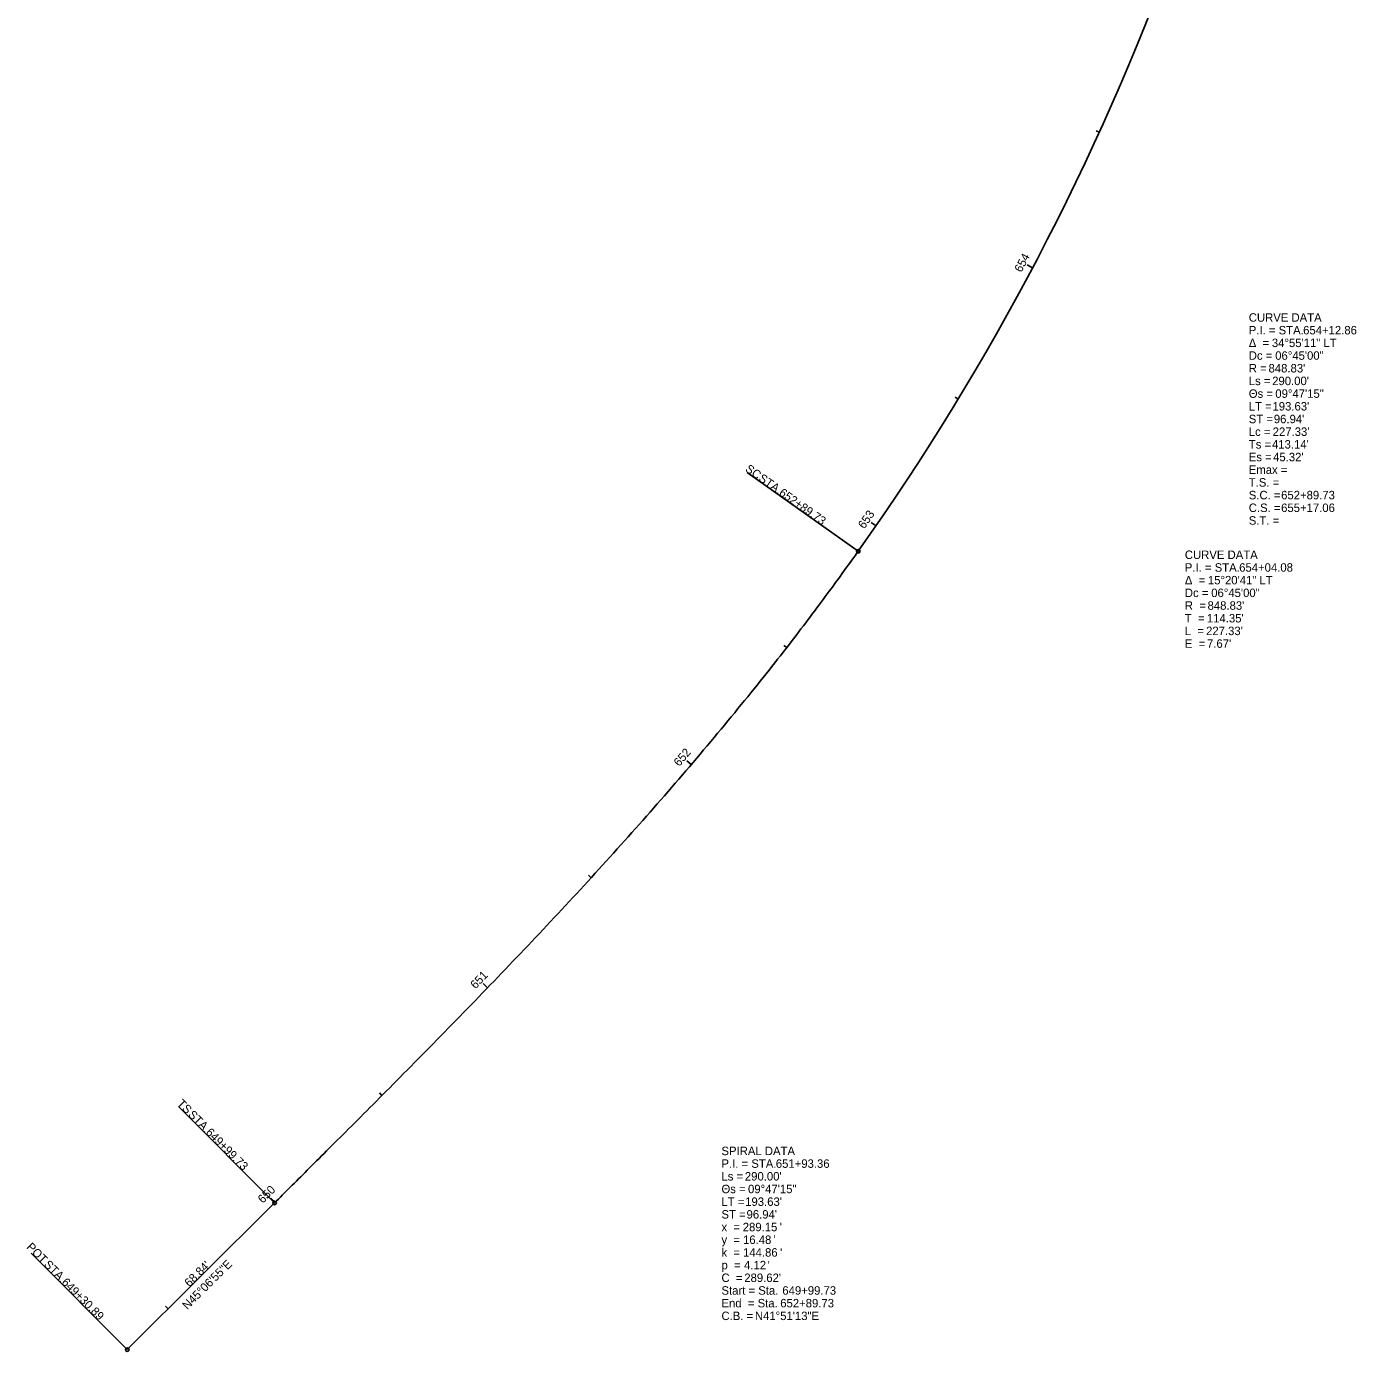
# Model space of a CAD drawing. Extents: x 171681 to 172332, y 456784 to 458794.
# Drawn here: x 171681.1 to 172121.4, y 456783.6 to 457222.2 of the extents above; entities that cross this region are included whole.
import ezdxf

# ---------------------------------------------------------------- set-up
doc = ezdxf.new("R2010")
doc.units = 0
for name, color, linetype in [('GE_X_Alignment', 7, 'Continuous'), ('GE_X_Alignment_100_Bearings', 7, 'Continuous'), ('GE_X_Alignment_100_Cardinal_Points', 7, 'Continuous'), ('GE_X_Alignment_100_Curve_Data', 7, 'Continuous'), ('GE_X_Alignment_100_Distances', 7, 'Continuous'), ('GE_X_Alignment_100_Stations', 7, 'Continuous')]:
    doc.layers.add(name, color=color, linetype=linetype)

msp = doc.modelspace()

# ---------------------------------------------------------------- linework, layer by layer
at = {"layer": 'GE_X_Alignment'}
msp.add_line((171714.41, 456784.19), (171763.18, 456832.76), dxfattribs=at)
msp.add_line((171714.41, 456784.19), (171763.18, 456832.76), dxfattribs=at)
msp.add_arc((171263.9, 457539.33), 848.83, 324.67218, 340.01698, dxfattribs=at)
msp.add_arc((171263.9, 457539.33), 848.83, 324.67218, 340.01698, dxfattribs=at)
msp.add_arc((171263.9, 457539.33), 848.83, 324.67218, 340.01698, dxfattribs=at)
msp.add_open_spline([(171763.18, 456832.76), (171766.6, 456836.17), (171773.45, 456842.99), (171787.14, 456856.65), (171804.2, 456873.76), (171824.54, 456894.44), (171844.67, 456915.32), (171864.5, 456936.47), (171883.97, 456957.97), (171903, 456979.85), (171921.5, 457002.19), (171936.41, 457021.22), (171947.97, 457036.71), (171953.63, 457044.55), (171956.43, 457048.49)], degree=3, dxfattribs=at)
msp.add_open_spline([(171763.18, 456832.76), (171766.6, 456836.17), (171773.45, 456842.99), (171787.14, 456856.65), (171804.2, 456873.76), (171824.54, 456894.44), (171844.67, 456915.32), (171864.5, 456936.47), (171883.97, 456957.97), (171903, 456979.85), (171921.5, 457002.19), (171936.41, 457021.22), (171947.97, 457036.71), (171953.63, 457044.55), (171956.43, 457048.49)], degree=3, dxfattribs=at)
msp.add_open_spline([(171763.18, 456832.76), (171766.6, 456836.17), (171773.45, 456842.99), (171787.14, 456856.65), (171804.2, 456873.76), (171824.54, 456894.44), (171844.67, 456915.32), (171864.5, 456936.47), (171883.97, 456957.97), (171903, 456979.85), (171921.5, 457002.19), (171936.41, 457021.22), (171947.97, 457036.71), (171953.63, 457044.55), (171956.43, 457048.49)], degree=3, dxfattribs=at)
at = {"layer": 'GE_X_Alignment_100_Cardinal_Points'}
for p, q in [((171956.43, 457048.49), (171919.71, 457074.51)), ((171763.18, 456832.76), (171731.42, 456864.65)), ((171714.41, 456784.19), (171682.65, 456816.07))]:
    msp.add_line(p, q, dxfattribs=at)
for centre in [(171956.43, 457048.49), (171763.18, 456832.76), (171714.41, 456784.19)]:
    msp.add_circle(centre, 0.6, dxfattribs=at)
at = {"layer": 'GE_X_Alignment_100_Stations'}
for p, q in [((172036.25, 457187.2), (172035.15, 457187.7)), ((172014.18, 457142.34), (172012.41, 457143.28)), ((171989.5, 457098.86), (171988.48, 457099.48)), ((171962.32, 457056.91), (171960.67, 457058.04)), ((171932.74, 457016.6), (171931.79, 457017.34)), ((171901.15, 456977.85), (171899.63, 456979.15)), ((171868.01, 456940.41), (171867.12, 456941.22)), ((171833.74, 456904), (171832.3, 456905.39)), ((171798.74, 456868.3), (171797.89, 456869.15)), ((171763.37, 456832.96), (171761.96, 456834.37)), ((171727.95, 456797.67), (171727.1, 456798.52))]:
    msp.add_line(p, q, dxfattribs=at)

# ---------------------------------------------------------------- texts
at = {"layer": 'GE_X_Alignment_100_Bearings'}
msp.add_text('N45°06\'55"E', height=2.8, rotation=44.8847, dxfattribs=at).set_placement((171734.3, 456797.23))
at = {"layer": 'GE_X_Alignment_100_Cardinal_Points'}
for s, rotation, p in [('SC', 324.6722, (171918.8, 457075.2)), (' STA. ', 324.6722, (171922.35, 457072.68)), ('652+89.73', 324.6722, (171929.96, 457067.29)), ('TS', 314.8847, (171730.73, 456865.4)), (' STA. ', 314.8847, (171733.63, 456862.48)), ('649+99.73', 314.8847, (171740.21, 456855.88)), ('POT', 314.8847, (171680.87, 456817.91)), (' STA. ', 314.8847, (171685.9, 456812.86)), ('649+30.89', 314.8847, (171692.48, 456806.25))]:
    msp.add_text(s, height=2.8, rotation=rotation, dxfattribs=at).set_placement(p)
at = {"layer": 'GE_X_Alignment_100_Curve_Data'}
for s, p in [('CURVE DATA', (172085.73, 457124.48)), ('P.I. = STA. ', (172085.73, 457120.28)), ('654+12.86', (172103.73, 457120.28)), ('Δ  = ', (172085.73, 457116.08)), ('34°55\'11" LT', (172093.38, 457116.08)), ('Dc = ', (172085.73, 457111.88)), ('06°45\'00"', (172094.48, 457111.88)), ('R = ', (172085.73, 457107.68)), ("848.83'", (172092.27, 457107.68)), ('Ls = ', (172085.73, 457103.48)), ("290.00'", (172093.48, 457103.48)), ('Θs = ', (172085.73, 457099.28)), ('09°47\'15"', (172094.52, 457099.28)), ('LT = ', (172085.73, 457095.08)), ("193.63'", (172093.58, 457095.08)), ('ST = ', (172085.73, 457090.88)), ("96.94'", (172094.03, 457090.88)), ('Lc = ', (172085.73, 457086.68)), ("227.33'", (172093.65, 457086.68)), ('Ts = ', (172085.73, 457082.48)), ("413.14'", (172093.42, 457082.48)), ('Es = ', (172085.73, 457078.28)), ("45.32'", (172093.79, 457078.28)), ('Emax = ', (172085.73, 457074.08)), ('T.S. = ', (172085.73, 457069.88)), ('S.C. = ', (172085.73, 457065.68)), ('652+89.73', (172096.44, 457065.68)), ('C.S. = ', (172085.73, 457061.48)), ('655+17.06', (172096.44, 457061.48)), ('S.T. = ', (172085.73, 457057.28)), ('CURVE DATA', (172064.56, 457045.92)), ('P.I. = STA. ', (172064.56, 457041.72)), ('654+04.08', (172082.55, 457041.72)), ('Δ  = ', (172064.56, 457037.52)), ('15°20\'41" LT', (172072.2, 457037.52)), ('Dc = ', (172064.56, 457033.32)), ('06°45\'00"', (172073.3, 457033.32)), ('R  = ', (172064.56, 457029.12)), ("848.83'", (172072.09, 457029.12)), ('T  = ', (172064.56, 457024.92)), ("114.35'", (172071.87, 457024.92)), ('L  = ', (172064.56, 457020.72)), ("227.33'", (172071.59, 457020.72)), ('E  = ', (172064.56, 457016.52)), ("7.67'", (172071.9, 457016.52)), ('SPIRAL DATA', (171911.15, 456848.56)), ('P.I. = STA. ', (171911.15, 456844.36)), ('651+93.36', (171929.14, 456844.36)), ('Ls = ', (171911.15, 456840.16)), ("290.00'", (171918.9, 456840.16)), ('Θs = ', (171911.15, 456835.96)), ('09°47\'15"', (171919.94, 456835.96)), ('LT = ', (171911.15, 456831.76)), ("193.63'", (171919, 456831.76)), ('ST = ', (171911.15, 456827.56)), ("96.94'", (171919.45, 456827.56)), ('x  = ', (171911.15, 456823.36)), ('289.15', (171918.19, 456823.36)), ('16.48', (171918.29, 456819.16)), ("'", (171928.3, 456819.16)), ("'", (171930.44, 456823.36)), ('y  = ', (171911.15, 456819.16)), ('k  = ', (171911.15, 456814.96)), ('144.86', (171918.29, 456814.96)), ("'", (171930.54, 456814.96)), ('4.12', (171918.63, 456810.76)), ("'", (171926.42, 456810.76)), ('C  = ', (171911.15, 456806.56)), ('p  = ', (171911.15, 456810.76)), ("289.62'", (171918.7, 456806.56)), ('Start = Sta. ', (171911.15, 456802.36)), ('649+99.73', (171931.3, 456802.36)), ('End  = Sta. ', (171911.15, 456798.16)), ('652+89.73', (171930.61, 456798.16)), ('C.B. = ', (171911.15, 456793.96)), ('N41°51\'13"E', (171922.22, 456793.96))]:
    msp.add_text(s, height=2.8, dxfattribs=at).set_placement(p)
at = {"layer": 'GE_X_Alignment_100_Distances'}
msp.add_text("68.84'", height=2.8, rotation=44.8847, dxfattribs=at).set_placement((171735, 456804.75))
at = {"layer": 'GE_X_Alignment_100_Stations'}
for s, rotation, p in [('654', 62.1157, (172010.43, 457140.61)), ('653', 55.3657, (171958.44, 457055.7)), ('652', 49.5526, (171897.16, 456977.03)), ('651', 46.0549, (171829.71, 456903.42)), ('650', 44.8847, (171759.29, 456832.42))]:
    msp.add_text(s, height=2.8, rotation=rotation, dxfattribs=at).set_placement(p)

doc.saveas('drawing.dxf')
